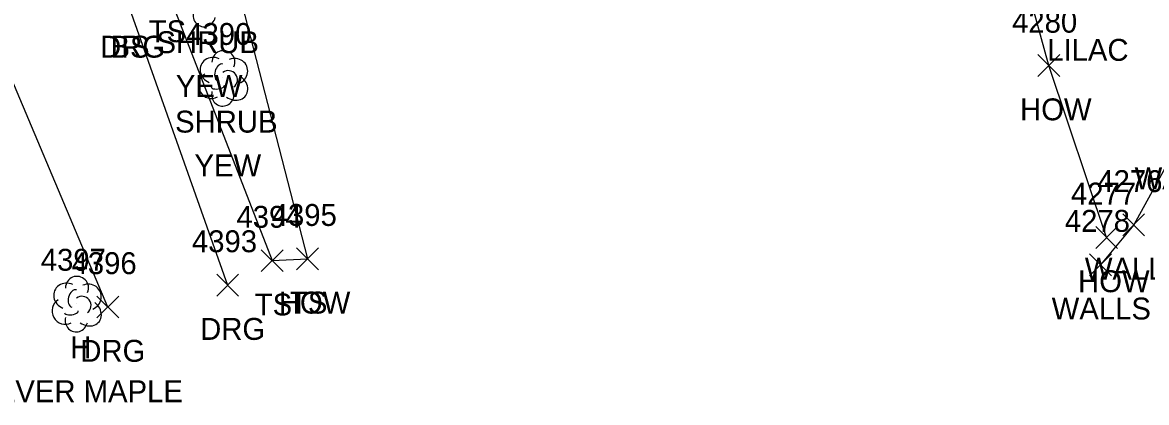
# Model space of a CAD drawing. Extents: x 1520648 to 1523413, y 732854 to 735518.
# Drawn here: x 1520739.3 to 1520842, y 733323.9 to 733358.5 of the extents above; entities that cross this region are included whole.
import ezdxf

# ---------------------------------------------------------------- set-up
doc = ezdxf.new("R2010")
doc.units = 0
for name, color, linetype in [('L_A', 7, 'Continuous'), ('L_C', 7, 'Continuous'), ('L_I', 7, 'Continuous'), ('L_TIC', 7, 'Continuous'), ('LBC', 7, 'Continuous'), ('LELB', 7, 'Continuous'), ('LSH', 7, 'Continuous'), ('LTD', 7, 'Continuous'), ('LWS', 7, 'Continuous'), ('R_A', 7, 'Continuous'), ('R_I', 7, 'Continuous'), ('R_TIC', 7, 'Continuous'), ('RDG', 7, 'Continuous')]:
    doc.layers.add(name, color=color, linetype=linetype)

msp = doc.modelspace()

# ---------------------------------------------------------------- linework, layer by layer
at = {"layer": 'L_TIC'}
for points in [[(1520832.04, 733353.62), (1520834.04, 733355.62)], [(1520834.04, 733353.62), (1520832.04, 733355.62)], [(1520839.8, 733339.07), (1520841.8, 733341.07)], [(1520841.8, 733339.07), (1520839.8, 733341.07)], [(1520837.33, 733337.93), (1520839.33, 733339.93)], [(1520839.33, 733337.93), (1520837.33, 733339.93)], [(1520761.08, 733335.81), (1520763.08, 733337.81)], [(1520763.08, 733335.81), (1520761.08, 733337.81)], [(1520764.3, 733335.98), (1520766.3, 733337.98)], [(1520766.3, 733335.98), (1520764.3, 733337.98)], [(1520764.3, 733335.98), (1520766.3, 733337.98)], [(1520766.3, 733335.98), (1520764.3, 733337.98)], [(1520836.77, 733335.44), (1520838.77, 733337.44)], [(1520838.77, 733335.44), (1520836.77, 733337.44)]]:
    msp.add_lwpolyline(points, dxfattribs=at)
at = {"layer": 'LBC'}
for points in [[(1520791.62, 733373.11), (1520779.81, 733370), (1520770.24, 733367.53), (1520758.26, 733364.31), (1520765.3, 733336.98)], [(1520838.33, 733338.93), (1520833.04, 733354.62), (1520828.27, 733372.02), (1520818.08, 733369.22)]]:
    msp.add_lwpolyline(points, dxfattribs=at)
at = {"layer": 'LELB'}
msp.add_lwpolyline([(1521084, 733484.54), (1521067.58, 733479.07), (1521049.77, 733473.83), (1520986.71, 733459.8), (1520946.37, 733448.2), (1520906.56, 733437.71), (1520887.62, 733432.82), (1520874.82, 733426.59), (1520851.23, 733419.6), (1520833.59, 733418.06), (1520824.1, 733415.79), (1520817.47, 733414.55), (1520789.23, 733404.3), (1520782.06, 733399.14), (1520771.54, 733396.06), (1520749.1, 733390.85), (1520744.37, 733386.94), (1520745.44, 733378.48), (1520749.8, 733369.39), (1520752.39, 733361.75), (1520762.08, 733336.81), (1520765.3, 733336.98)], dxfattribs=at)
at = {"layer": 'LSH'}
msp.add_line((1520757.58, 733353.5), (1520757.58, 733353.5), dxfattribs=at)
msp.add_line((1520757.58, 733353.5), (1520757.58, 733353.5), dxfattribs=at)
msp.add_arc((1520757.63, 733354.93), 1.05, 335.5272, 180.9563, dxfattribs=at)
for centre, major_axis, ratio, start_param, end_param in [((1520755.88, 733359.25), (0.26, 1.06), 0.942809, 1.570796, 4.712389), ((1520756.79, 733354.16), (1.21, -0.51), 0.895232, 1.570796, 4.712389), ((1520758.62, 733354.08), (-1.14, -0.48), 0.949671, 1.570796, 4.712389), ((1520757.37, 733353.96), (-0.208, -0.792), 0.645439, 3.141593, 6.283185), ((1520758.08, 733353.33), (-0.5, 0.667), 0.989748, 3.141593, 6.283185), ((1520756.5, 733352.79), (0.58, -1.04), 0.959034, 3.141593, 6.283185), ((1520758.58, 733352.66), (-1.09, 0.79), 0.841452, 1.570796, 4.712389), ((1520757.58, 733352), (0.26, 1.06), 0.942809, 1.570796, 4.712389), ((1520757.12, 733352.75), (-0.625, -0.083), 0.423636, 0, 3.141593)]:
    msp.add_ellipse(centre, major_axis=major_axis, ratio=ratio, start_param=start_param, end_param=end_param, dxfattribs=at)
at = {"layer": 'LTD'}
msp.add_line((1520744.2, 733332.89), (1520744.2, 733332.89), dxfattribs=at)
msp.add_line((1520744.2, 733332.89), (1520744.2, 733332.89), dxfattribs=at)
msp.add_arc((1520744.25, 733334.33), 1.05, 335.5272, 180.9563, dxfattribs=at)
for centre, major_axis, ratio, start_param, end_param in [((1520743.41, 733333.56), (1.21, -0.51), 0.895232, 1.570796, 4.712389), ((1520745.24, 733333.48), (-1.14, -0.48), 0.949671, 1.570796, 4.712389), ((1520743.99, 733333.35), (-0.208, -0.792), 0.645439, 3.141593, 6.283185), ((1520744.7, 733332.73), (-0.5, 0.667), 0.989748, 3.141593, 6.283185), ((1520743.12, 733332.18), (0.58, -1.04), 0.959034, 3.141593, 6.283185), ((1520745.2, 733332.06), (-1.09, 0.79), 0.841452, 1.570796, 4.712389), ((1520744.2, 733331.39), (0.26, 1.06), 0.942809, 1.570796, 4.712389), ((1520743.74, 733332.14), (-0.625, -0.083), 0.423636, 0, 3.141593)]:
    msp.add_ellipse(centre, major_axis=major_axis, ratio=ratio, start_param=start_param, end_param=end_param, dxfattribs=at)
at = {"layer": 'LWS'}
msp.add_lwpolyline([(1520845.35, 733348.33), (1520840.8, 733340.07), (1520837.77, 733336.44)], dxfattribs=at)
at = {"layer": 'R_TIC'}
for points in [[(1520757.01, 733333.58), (1520759.01, 733335.58)], [(1520759.01, 733333.58), (1520757.01, 733335.58)], [(1520746.06, 733331.58), (1520748.06, 733333.58)], [(1520748.06, 733331.58), (1520746.06, 733333.58)]]:
    msp.add_lwpolyline(points, dxfattribs=at)
at = {"layer": 'RDG'}
for points in [[(1520743.14, 733395.11), (1520740.34, 733389.92), (1520748.87, 733360.34), (1520758.01, 733334.58)], [(1520747.06, 733332.58), (1520735.54, 733359.77), (1520724.39, 733378.64), (1520721.49, 733386.26), (1520720.82, 733389.47)]]:
    msp.add_lwpolyline(points, dxfattribs=at)

# ---------------------------------------------------------------- texts
at = {"layer": 'L_A'}
for s, p in [('TS', (1520750.8, 733356.75)), ('BS', (1520747.31, 733355.34)), ('SHRUB', (1520751.51, 733355.75)), ('HOW', (1520830.42, 733349.62)), ('SHRUB', (1520753.21, 733348.5)), ('WALLS', (1520840.89, 733343.33)), ('WALLS', (1520836.34, 733335.07)), ('HOW', (1520835.72, 733333.93)), ('TS', (1520760.49, 733331.81)), ('HOW', (1520762.69, 733331.98)), ('TS', (1520763.71, 733331.98)), ('WALLS', (1520833.31, 733331.44)), ('H', (1520743.63, 733327.89))]:
    msp.add_text(s, height=2, dxfattribs=at).set_placement(p)
at = {"layer": 'L_C'}
for s, p in [('LILAC', (1520832.9, 733355.05)), ('YEW', (1520753.28, 733351.75)), ('YEW', (1520754.98, 733344.5)), ('L.SILVER MAPLE', (1520732.37, 733323.89))]:
    msp.add_text(s, height=2, dxfattribs=at).set_placement(p)
at = {"layer": 'L_I'}
for s, p in [('4280', (1520829.69, 733357.62)), ('4390', (1520754.23, 733356.5)), ('4276', (1520837.48, 733343.07)), ('4277', (1520835.07, 733341.93)), ('4394', (1520758.82, 733339.81)), ('4395', (1520762.04, 733339.98)), ('4395', (1520762.04, 733339.98)), ('4278', (1520834.51, 733339.44)), ('4397', (1520740.94, 733335.89))]:
    msp.add_text(s, height=2, dxfattribs=at).set_placement(p)
at = {"layer": 'R_A'}
for p in [(1520746.36, 733355.34), (1520755.5, 733329.58), (1520744.55, 733327.58)]:
    msp.add_text('DRG', height=2, dxfattribs=at).set_placement(p)
at = {"layer": 'R_I'}
for s, p in [('4393', (1520754.75, 733337.58)), ('4396', (1520743.75, 733335.58))]:
    msp.add_text(s, height=2, dxfattribs=at).set_placement(p)

doc.saveas('drawing.dxf')
